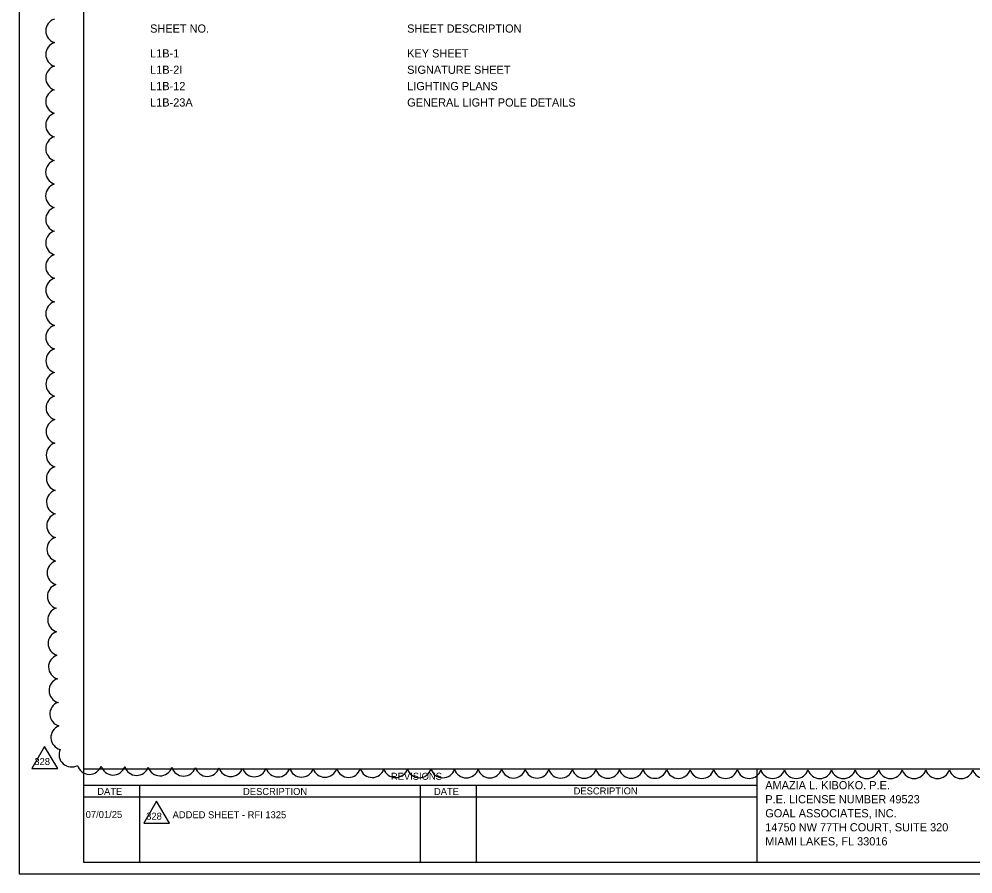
# Model space of a CAD drawing. Extents: x -811.2 to -755.6, y -2295.2 to -2235.1.
# Drawn here: x -783.91 to -775.75, y -2282.95 to -2275.63 of the extents above; entities that cross this region are included whole.
import ezdxf

# ---------------------------------------------------------------- set-up
doc = ezdxf.new("R2010")
doc.units = 0
for name, color, linetype in [('Cloud_dp', 7, 'Continuous'), ('PlotBorder_dp', 7, 'Continuous'), ('SheetBorder_dp', 7, 'Continuous'), ('SheetLines_dp', 7, 'Continuous'), ('TextMinor', 7, 'Continuous'), ('TextMisc', 7, 'Continuous'), ('TextNotes', 7, 'Continuous'), ('TextTitle', 7, 'Continuous')]:
    doc.layers.add(name, color=color, linetype=linetype)

msp = doc.modelspace()

# ---------------------------------------------------------------- linework, layer by layer
at = {"layer": 'Cloud_dp'}
for points in [[(-783.6889, -2281.8566), (-783.7966, -2282.0447), (-783.576, -2282.0447)], [(-782.7321, -2282.3241), (-782.8398, -2282.5122), (-782.6192, -2282.5122)]]:
    msp.add_lwpolyline(points, close=True, dxfattribs=at)
for centre, start, end in [((-783.5726, -2275.7344), 107.45847, 252.45847), ((-783.5727, -2275.9359), 107.46563, 252.46563), ((-783.5728, -2276.1375), 107.47218, 252.47218), ((-783.5729, -2276.339), 107.47822, 252.47822), ((-783.573, -2276.5406), 107.4838, 252.4838), ((-783.573, -2276.7421), 107.48899, 252.48899), ((-783.5731, -2276.9436), 107.49382, 252.49382), ((-783.5731, -2277.1452), 107.49843, 252.49843), ((-783.573, -2277.3467), 107.51148, 252.51148), ((-783.573, -2277.5483), 107.53101, 252.53101), ((-783.5728, -2277.7498), 107.55191, 252.55191), ((-783.5726, -2277.9513), 107.57435, 252.57435), ((-783.5723, -2278.1529), 107.59852, 252.59852), ((-783.5719, -2278.3544), 107.62468, 252.62468), ((-783.5714, -2278.5559), 107.65309, 252.65309), ((-783.5708, -2278.7575), 107.68411, 252.68411), ((-783.5701, -2278.959), 107.71817, 252.71817), ((-783.5693, -2279.1605), 107.75578, 252.75578), ((-783.5683, -2279.3621), 107.79762, 252.79762), ((-783.5672, -2279.5636), 107.84454, 252.84454), ((-783.5659, -2279.7651), 107.89767, 252.89767), ((-783.5644, -2279.9666), 107.95851, 252.95851), ((-783.5626, -2280.1681), 108.02912, 253.02912), ((-783.5606, -2280.3696), 108.11243, 253.11243), ((-783.5583, -2280.5711), 108.21279, 253.21279), ((-783.5556, -2280.7725), 108.33694, 253.33694), ((-783.5523, -2280.974), 108.49611, 253.49611), ((-783.5485, -2281.1754), 108.71068, 253.71068), ((-783.5437, -2281.3767), 109.02298, 254.02298), ((-783.5374, -2281.5778), 109.54201, 254.54201), ((-783.5282, -2281.7785), 110.71007, 255.71007), ((-783.4585, -2281.9255), 155.06518, 300.06518), ((-783.3038, -2281.9884), 195.62937, 340.62937), ((-783.1027, -2281.9939), 196.26473, 341.26473), ((-782.9013, -2281.9977), 196.54985, 341.54985), ((-782.6999, -2282.0008), 196.72204, 341.72204), ((-782.4984, -2282.0033), 196.84059, 341.84059), ((-782.2969, -2282.0055), 196.92865, 341.92865), ((-782.0954, -2282.0073), 196.99739, 341.99739), ((-781.8939, -2282.009), 197.053, 342.053), ((-781.6924, -2282.0105), 197.09919, 342.09919), ((-781.4909, -2282.0118), 197.13834, 342.13834), ((-781.2893, -2282.0131), 197.17209, 342.17209), ((-781.0878, -2282.0142), 197.20158, 342.20158), ((-780.8863, -2282.0152), 197.22762, 342.22762), ((-780.6847, -2282.0161), 197.25085, 342.25085), ((-780.4832, -2282.0169), 197.27174, 342.27174), ((-780.2817, -2282.0177), 197.29065, 342.29065), ((-780.0801, -2282.0184), 197.30788, 342.30788), ((-779.8786, -2282.019), 197.32367, 342.32367), ((-779.6771, -2282.0196), 197.3382, 342.3382), ((-779.4755, -2282.0202), 197.35163, 342.35163), ((-779.274, -2282.0207), 197.3641, 342.3641), ((-779.0724, -2282.0211), 197.37571, 342.37571), ((-778.8709, -2282.0216), 197.38657, 342.38657), ((-778.6693, -2282.0219), 197.39674, 342.39674), ((-778.4678, -2282.0223), 197.40629, 342.40629), ((-778.2663, -2282.0226), 197.4153, 342.4153), ((-778.0647, -2282.0229), 197.4238, 342.4238), ((-777.8632, -2282.0231), 197.43184, 342.43184), ((-777.6616, -2282.0234), 197.43947, 342.43947), ((-777.4601, -2282.0236), 197.44671, 342.44671), ((-777.2585, -2282.0237), 197.4536, 342.4536), ((-777.057, -2282.0239), 197.46017, 342.46017), ((-776.8554, -2282.024), 197.46644, 342.46644), ((-776.6539, -2282.0241), 197.47243, 342.47243), ((-776.4524, -2282.0242), 197.47816, 342.47816), ((-776.2508, -2282.0243), 197.48365, 342.48365), ((-776.0493, -2282.0243), 197.48892, 342.48892), ((-775.8477, -2282.0244), 197.49398, 342.49398), ((-775.6462, -2282.0244), 197.49888, 342.49888)]:
    msp.add_arc(centre, 0.1057, start, end, dxfattribs=at)
at = {"layer": 'PlotBorder_dp'}
msp.add_lwpolyline([(-783.9062, -2282.9457), (-767.4062, -2282.9457), (-767.4062, -2272.3457), (-783.9062, -2272.3457)], close=True, dxfattribs=at)
at = {"layer": 'SheetBorder_dp'}
for p, q in [((-783.3562, -2272.4457), (-783.3562, -2282.8457)), ((-783.3562, -2282.0457), (-767.9562, -2282.0457)), ((-783.3562, -2282.8457), (-767.9562, -2282.8457))]:
    msp.add_line(p, q, dxfattribs=at)
at = {"layer": 'SheetLines_dp'}
for p, q in [((-777.5962, -2282.0457), (-777.5962, -2282.8457)), ((-783.3562, -2282.1857), (-777.5962, -2282.1857)), ((-782.8762, -2282.1857), (-782.8762, -2282.8457)), ((-780.4762, -2282.1857), (-780.4762, -2282.8457)), ((-779.9962, -2282.1857), (-779.9962, -2282.8457)), ((-783.3562, -2282.2857), (-777.5962, -2282.2857))]:
    msp.add_line(p, q, dxfattribs=at)

# ---------------------------------------------------------------- texts
at = {"layer": 'Cloud_dp'}
for p in [(-783.7755, -2282.0146), (-782.8187, -2282.482)]:
    msp.add_text('328', height=0.05998, rotation=0, dxfattribs=at).set_placement(p)
at = {"layer": 'TextMinor'}
for s, p in [('07/01/25', (-783.3365, -2282.4672)), ('ADDED SHEET - RFI 1325', (-782.593, -2282.4696))]:
    msp.add_text(s, height=0.06, dxfattribs=at).set_placement(p)
at = {"layer": 'TextMisc'}
msp.add_text('REVISIONS', height=0.06, dxfattribs=at).set_placement((-780.7257, -2282.1406))
for s, rotation, p in [('DATE', 359.86925, (-783.2373, -2282.2697)), ('DESCRIPTION', 0.04975, (-781.9903, -2282.2709)), ('DATE', 359.86925, (-780.3573, -2282.2704)), ('DESCRIPTION', 0.04975, (-779.1626, -2282.266))]:
    msp.add_text(s, height=0.06, rotation=rotation, dxfattribs=at).set_placement(p)
at = {"layer": 'TextNotes'}
for s, p in [('SHEET NO.', (-782.7855, -2275.7495)), ('SHEET DESCRIPTION', (-780.5865, -2275.7495)), ('L1B-1', (-782.7855, -2275.9617)), ('KEY SHEET', (-780.5865, -2275.9617)), ('L1B-2I', (-782.7855, -2276.1017)), ('SIGNATURE SHEET', (-780.5865, -2276.1017)), ('L1B-12', (-782.7855, -2276.2417)), ('LIGHTING PLANS', (-780.5865, -2276.2417)), ('L1B-23A', (-782.7855, -2276.3817)), ('GENERAL LIGHT POLE DETAILS', (-780.5865, -2276.3817))]:
    msp.add_text(s, height=0.07, dxfattribs=at).set_placement(p)
at = {"layer": 'TextTitle'}
for s, p in [('AMAZIA L. KIBOKO. P.E.', (-777.5233, -2282.2218)), ('P.E. LICENSE NUMBER 49523', (-777.5233, -2282.3418)), ('GOAL ASSOCIATES, INC.', (-777.5233, -2282.4618)), ('14750 NW 77TH COURT, SUITE 320', (-777.5233, -2282.5818)), ('MIAMI LAKES, FL 33016', (-777.5233, -2282.7018))]:
    msp.add_text(s, height=0.07, dxfattribs=at).set_placement(p)

doc.saveas('drawing.dxf')
